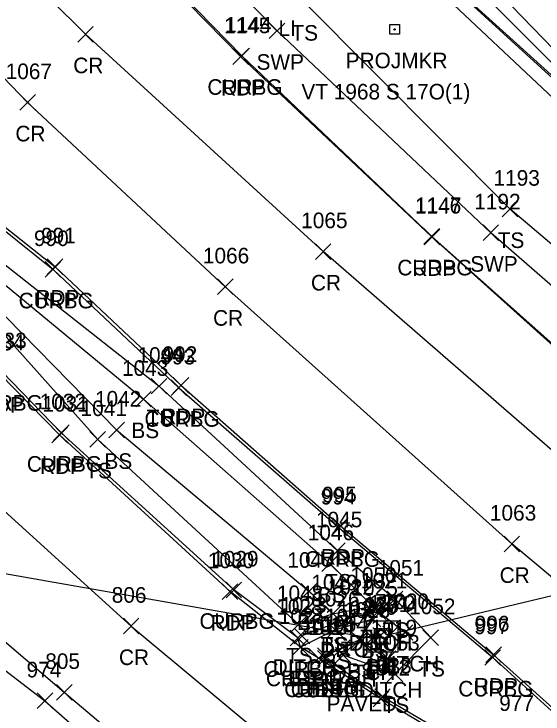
# Model space of a CAD drawing. Extents: x 1688195 to 1692013, y 424605 to 441234.
# Drawn here: x 1691823.2 to 1691891.2, y 439243.2 to 439333.1 of the extents above; entities that cross this region are included whole.
import ezdxf

# ---------------------------------------------------------------- set-up
doc = ezdxf.new("R2010")
doc.units = 0
for name, color, linetype in [('D_A', 7, 'Continuous'), ('D_C', 7, 'Continuous'), ('D_I', 7, 'Continuous'), ('D_TIC', 7, 'Continuous'), ('DCP', 7, 'Continuous'), ('DD', 7, 'Continuous'), ('DS', 7, 'Continuous'), ('L_A', 7, 'Continuous'), ('L_I', 7, 'Continuous'), ('L_TIC', 7, 'Continuous'), ('LELB', 7, 'Continuous'), ('P_A', 7, 'Continuous'), ('P_I', 7, 'Continuous'), ('P_TIC', 7, 'Continuous'), ('PET', 7, 'Continuous'), ('PRC', 7, 'Continuous'), ('PSP', 7, 'Continuous'), ('R_A', 7, 'Continuous'), ('R_I', 7, 'Continuous'), ('R_TIC', 7, 'Continuous'), ('RC', 7, 'Continuous'), ('RSW', 7, 'Continuous'), ('S_A', 7, 'Continuous'), ('S_C', 7, 'Continuous'), ('S_I', 7, 'Continuous'), ('SRM', 7, 'Continuous'), ('U_A', 7, 'Continuous')]:
    doc.layers.add(name, color=color, linetype=linetype)

msp = doc.modelspace()

# ---------------------------------------------------------------- linework, layer by layer
at = {"layer": 'D_TIC'}
for points in [[(1691869.012, 439255.339), (1691871.012, 439257.339)], [(1691871.012, 439255.339), (1691869.012, 439257.339)], [(1691865.312, 439254.525), (1691867.312, 439256.525)], [(1691867.312, 439254.525), (1691865.312, 439256.525)], [(1691859.231, 439252.243), (1691861.231, 439254.243)], [(1691861.231, 439252.243), (1691859.231, 439254.243)], [(1691869.335, 439252.313), (1691871.335, 439254.313)], [(1691871.335, 439252.313), (1691869.335, 439254.313)], [(1691870.629, 439252.485), (1691872.629, 439254.485)], [(1691872.629, 439252.485), (1691870.629, 439254.485)], [(1691872.466, 439252.691), (1691874.466, 439254.691)], [(1691874.466, 439252.691), (1691872.466, 439254.691)], [(1691866.813, 439251.57), (1691868.813, 439253.57)], [(1691868.813, 439251.57), (1691866.813, 439253.57)], [(1691868.305, 439251.966), (1691870.305, 439253.966)], [(1691870.305, 439251.966), (1691868.305, 439253.966)], [(1691864.421, 439250.736), (1691866.421, 439252.736)], [(1691866.421, 439250.736), (1691864.421, 439252.736)], [(1691862.225, 439249.714), (1691864.225, 439251.714)], [(1691864.225, 439249.714), (1691862.225, 439251.714)], [(1691870.288, 439249.327), (1691872.288, 439251.327)], [(1691872.288, 439249.327), (1691870.288, 439251.327)]]:
    msp.add_lwpolyline(points, dxfattribs=at)
at = {"layer": 'DCP'}
for points in [[(1691949.159, 439273.864), (1691789.035, 439418.458)], [(1691774.059, 439269.686), (1691869.305, 439252.966)], [(1691871.629, 439253.485), (1691919.551, 439264.923)]]:
    msp.add_lwpolyline(points, dxfattribs=at)
at = {"layer": 'DD'}
for points in [[(1691845.001, 439386.653), (1691846.957, 439371.914), (1691853.76, 439362.044), (1691874.032, 439339.657), (1691896.104, 439318.91), (1691934.444, 439282.927), (1691949.727, 439270.289), (1691969.734, 439279.956), (1691978.582, 439270.803)], [(1691849.482, 439383.397), (1691851.476, 439372.687), (1691857.963, 439364.796), (1691877.631, 439343.986), (1691899.361, 439321.571), (1691937.96, 439287.208), (1691947.813, 439278.163), (1691953.235, 439277.559), (1691972.915, 439286.296), (1691980.771, 439274.159), (1691984.62, 439267.717)], [(1691863.225, 439250.714), (1691865.421, 439251.736), (1691867.813, 439252.57), (1691871.288, 439250.327), (1691873.466, 439253.691), (1691870.012, 439256.339), (1691866.312, 439255.525), (1691860.231, 439253.243)]]:
    msp.add_lwpolyline(points, dxfattribs=at)
at = {"layer": 'DS'}
for p, q in [((1691868.561, 439255.182), (1691872.561, 439255.182)), ((1691868.561, 439251.182), (1691868.561, 439255.182)), ((1691872.561, 439255.182), (1691872.561, 439251.182)), ((1691869.561, 439252.182), (1691869.561, 439254.182)), ((1691869.561, 439254.182), (1691871.561, 439254.182)), ((1691871.561, 439254.182), (1691871.561, 439252.182)), ((1691870.566, 439253.183), (1691870.566, 439253.183)), ((1691870.566, 439253.183), (1691870.566, 439253.183)), ((1691871.561, 439252.182), (1691869.561, 439252.182)), ((1691872.561, 439251.182), (1691868.561, 439251.182))]:
    msp.add_line(p, q, dxfattribs=at)
at = {"layer": 'L_TIC'}
for points in [[(1691885.972, 439307.046), (1691887.972, 439309.046)], [(1691887.972, 439307.046), (1691885.972, 439309.046)], [(1691840.88, 439284.31), (1691842.88, 439286.31)], [(1691842.88, 439284.31), (1691840.88, 439286.31)], [(1691838.882, 439282.636), (1691840.882, 439284.636)], [(1691840.882, 439282.636), (1691838.882, 439284.636)], [(1691835.42, 439278.689), (1691837.42, 439280.689)], [(1691837.42, 439278.689), (1691835.42, 439280.689)], [(1691832.998, 439277.476), (1691834.998, 439279.476)], [(1691834.998, 439277.476), (1691832.998, 439279.476)], [(1691863.803, 439263.192), (1691865.803, 439265.192)], [(1691865.803, 439263.192), (1691863.803, 439265.192)], [(1691862.807, 439261.535), (1691864.807, 439263.535)], [(1691864.807, 439261.535), (1691862.807, 439263.535)], [(1691860.134, 439257.993), (1691862.134, 439259.993)], [(1691862.134, 439257.993), (1691860.134, 439259.993)], [(1691871.176, 439256.99), (1691873.176, 439258.99)], [(1691873.176, 439256.99), (1691871.176, 439258.99)], [(1691868.31, 439256.053), (1691870.31, 439258.053)], [(1691870.31, 439256.053), (1691868.31, 439258.053)], [(1691868.31, 439256.053), (1691870.31, 439258.053)], [(1691870.31, 439256.053), (1691868.31, 439258.053)], [(1691863.22, 439255.101), (1691865.22, 439257.101)], [(1691865.22, 439255.101), (1691863.22, 439257.101)], [(1691863.22, 439255.101), (1691865.22, 439257.101)], [(1691865.22, 439255.101), (1691863.22, 439257.101)], [(1691868.369, 439254.401), (1691870.369, 439256.401)], [(1691870.369, 439254.401), (1691868.369, 439256.401)], [(1691858.792, 439253.715), (1691860.792, 439255.715)], [(1691860.792, 439253.715), (1691858.792, 439255.715)], [(1691863.516, 439253.027), (1691865.516, 439255.027)], [(1691865.516, 439253.027), (1691863.516, 439255.027)], [(1691866.598, 439251.737), (1691868.598, 439253.737)], [(1691868.598, 439251.737), (1691866.598, 439253.737)], [(1691875.774, 439252.036), (1691877.774, 439254.036)], [(1691877.774, 439252.036), (1691875.774, 439254.036)], [(1691859.033, 439250.797), (1691861.033, 439252.797)], [(1691861.033, 439250.797), (1691859.033, 439252.797)], [(1691864.531, 439249.784), (1691866.531, 439251.784)], [(1691866.531, 439249.784), (1691864.531, 439251.784)], [(1691861.377, 439249.392), (1691863.377, 439251.392)], [(1691863.377, 439249.392), (1691861.377, 439251.392)], [(1691871.187, 439247.373), (1691873.187, 439249.373)], [(1691873.187, 439247.373), (1691871.187, 439249.373)]]:
    msp.add_lwpolyline(points, dxfattribs=at)
at = {"layer": 'LELB'}
for points in [[(1691975.613, 439270.604), (1691971.416, 439266.02), (1691960.529, 439259.243), (1691939.22, 439264.039), (1691915.683, 439283.723), (1691886.972, 439308.046), (1691860.472, 439334.665), (1691845.989, 439348.301), (1691840.055, 439356.702), (1691834.354, 439370.122), (1691833.776, 439391.583)], [(1691846.65, 439384.738), (1691848.676, 439371.881), (1691855.161, 439363.031), (1691875.02, 439340.722), (1691897.71, 439320.027), (1691935.729, 439284.323), (1691949.052, 439272.369), (1691970.057, 439281.458), (1691980.121, 439271.732), (1691983.031, 439266.506)], [(1691847.582, 439384.469), (1691849.654, 439372.104), (1691856.364, 439363.867), (1691876.408, 439342.833), (1691898.398, 439320.717), (1691936.438, 439285.395), (1691950.074, 439275.355), (1691972.127, 439284.543), (1691980.121, 439271.732)], [(1691816.816, 439305.046), (1691813.249, 439301.655), (1691833.998, 439278.476), (1691859.792, 439254.715), (1691864.22, 439256.101), (1691869.31, 439257.053)], [(1691816.816, 439305.046), (1691841.88, 439285.31), (1691864.803, 439264.192), (1691872.176, 439257.99), (1691876.774, 439253.036), (1691872.187, 439248.373), (1691865.531, 439250.784)], [(1691819.881, 439300.105), (1691818.164, 439298.257), (1691836.42, 439279.689), (1691861.134, 439258.993), (1691864.22, 439256.101)], [(1691819.881, 439300.105), (1691839.882, 439283.636), (1691863.807, 439262.535), (1691869.31, 439257.053)], [(1691862.377, 439250.392), (1691867.598, 439252.737), (1691869.369, 439255.401), (1691864.516, 439254.027), (1691860.033, 439251.797)]]:
    msp.add_lwpolyline(points, dxfattribs=at)
at = {"layer": 'P_TIC'}
for points in [[(1691831.423, 439329.487), (1691833.423, 439331.487)], [(1691833.423, 439329.487), (1691831.423, 439331.487)], [(1691851.353, 439326.623), (1691853.353, 439328.623)], [(1691853.353, 439326.623), (1691851.353, 439328.623)], [(1691823.991, 439320.732), (1691825.991, 439322.732)], [(1691825.991, 439320.732), (1691823.991, 439322.732)], [(1691875.927, 439303.468), (1691877.927, 439305.468)], [(1691877.927, 439303.468), (1691875.927, 439305.468)], [(1691861.957, 439301.592), (1691863.957, 439303.592)], [(1691863.957, 439301.592), (1691861.957, 439303.592)], [(1691827.512, 439299.647), (1691829.512, 439301.647)], [(1691829.512, 439299.647), (1691827.512, 439301.647)], [(1691849.384, 439297.072), (1691851.384, 439299.072)], [(1691851.384, 439297.072), (1691849.384, 439299.072)], [(1691843.684, 439284.422), (1691845.684, 439286.422)], [(1691845.684, 439284.422), (1691843.684, 439286.422)], [(1691828.097, 439278.042), (1691830.097, 439280.042)], [(1691830.097, 439278.042), (1691828.097, 439280.042)], [(1691864.174, 439266.394), (1691866.174, 439268.394)], [(1691866.174, 439266.394), (1691864.174, 439268.394)], [(1691886.198, 439264.051), (1691888.198, 439266.051)], [(1691888.198, 439264.051), (1691886.198, 439266.051)], [(1691850.002, 439257.938), (1691852.002, 439259.938)], [(1691852.002, 439257.938), (1691850.002, 439259.938)], [(1691837.297, 439253.51), (1691839.297, 439255.51)], [(1691839.297, 439253.51), (1691837.297, 439255.51)], [(1691859.033, 439250.797), (1691861.033, 439252.797)], [(1691861.033, 439250.797), (1691859.033, 439252.797)], [(1691883.848, 439249.831), (1691885.848, 439251.831)], [(1691885.848, 439249.831), (1691883.848, 439251.831)], [(1691861.377, 439249.392), (1691863.377, 439251.392)], [(1691863.377, 439249.392), (1691861.377, 439251.392)], [(1691828.698, 439245.009), (1691830.698, 439247.009)], [(1691830.698, 439245.009), (1691828.698, 439247.009)], [(1691869.381, 439244.165), (1691871.381, 439246.165)], [(1691871.381, 439244.165), (1691869.381, 439246.165)], [(1691826.219, 439243.924), (1691828.219, 439245.924)], [(1691828.219, 439243.924), (1691826.219, 439245.924)]]:
    msp.add_lwpolyline(points, dxfattribs=at)
at = {"layer": 'PET'}
for points in [[(1691827.559, 439394.955), (1691825.961, 439390.443), (1691824.493, 439382.805), (1691824.197, 439378.066), (1691824.28, 439373.817), (1691824.909, 439368.552), (1691826.714, 439361.575), (1691828.277, 439357.551), (1691830.285, 439353.486), (1691834.62, 439346.713), (1691838.982, 439341.279), (1691852.353, 439327.623), (1691876.927, 439304.468), (1691895.87, 439287.457)], [(1691703.519, 439378.215), (1691727.927, 439348.964), (1691752.514, 439320.765), (1691774.827, 439296.788), (1691803.993, 439267.935), (1691829.698, 439246.009), (1691860.192, 439220.256)], [(1691800.945, 439315.05), (1691800.709, 439316.533), (1691801.542, 439317.586), (1691803.007, 439317.751), (1691817.064, 439309.697), (1691828.512, 439300.647), (1691844.684, 439285.422), (1691865.174, 439267.394), (1691884.848, 439250.831), (1691897.532, 439239.425), (1691910.299, 439227.429), (1691911.518, 439225.273), (1691910.888, 439223.79), (1691909.812, 439223.418), (1691908.764, 439223.597), (1691890.09, 439233.403), (1691870.381, 439245.165), (1691862.377, 439250.392), (1691860.033, 439251.797), (1691851.002, 439258.938), (1691829.097, 439279.042), (1691821.385, 439286.908), (1691810.775, 439300.426)]]:
    msp.add_lwpolyline(points, dxfattribs=at)
at = {"layer": 'PRC'}
for points in [[(1691980.661, 439193.959), (1691949.028, 439215.605), (1691915.391, 439241.551), (1691887.198, 439265.051), (1691850.384, 439298.072), (1691824.991, 439321.732), (1691796.941, 439350.893), (1691771.504, 439379.218), (1691742.052, 439414.412)], [(1691713.182, 439386.477), (1691737.313, 439357.714), (1691761.172, 439330.745), (1691784.31, 439305.517), (1691812.134, 439278.202), (1691838.297, 439254.51), (1691867.441, 439230.247), (1691889.259, 439214.415), (1691920.444, 439189.798), (1691954.552, 439163.68)], [(1691957.024, 439223.443), (1691923.547, 439249.723), (1691894.348, 439275.353), (1691862.957, 439302.592), (1691832.423, 439330.487), (1691805.17, 439357.497)]]:
    msp.add_lwpolyline(points, dxfattribs=at)
at = {"layer": 'PSP'}
msp.add_lwpolyline([(1691696.132, 439372.686), (1691709.548, 439355.191), (1691723.603, 439339.325), (1691742.747, 439319), (1691750.974, 439309.526), (1691763.384, 439297.713), (1691773.94, 439286.942), (1691807.317, 439260.152), (1691827.219, 439244.924), (1691853.912, 439221.372)], dxfattribs=at)
at = {"layer": 'R_TIC'}
for points in [[(1691856.041, 439329.929), (1691858.041, 439331.929)], [(1691858.041, 439329.929), (1691856.041, 439331.929)], [(1691851.504, 439326.715), (1691853.504, 439328.715)], [(1691853.504, 439326.715), (1691851.504, 439328.715)], [(1691875.907, 439303.531), (1691877.907, 439305.531)], [(1691877.907, 439303.531), (1691875.907, 439305.531)], [(1691883.494, 439304.003), (1691885.494, 439306.003)], [(1691885.494, 439304.003), (1691883.494, 439306.003)], [(1691827.254, 439299.3), (1691829.254, 439301.3)], [(1691829.254, 439299.3), (1691827.254, 439301.3)], [(1691843.418, 439284.107), (1691845.418, 439286.107)], [(1691845.418, 439284.107), (1691843.418, 439286.107)], [(1691828.315, 439278.332), (1691830.315, 439280.332)], [(1691830.315, 439278.332), (1691828.315, 439280.332)], [(1691864.016, 439266.121), (1691866.016, 439268.121)], [(1691866.016, 439266.121), (1691864.016, 439268.121)], [(1691850.486, 439258.157), (1691852.486, 439260.157)], [(1691852.486, 439258.157), (1691850.486, 439260.157)], [(1691858.706, 439251.995), (1691860.706, 439253.995)], [(1691860.706, 439251.995), (1691858.706, 439253.995)], [(1691859.033, 439250.797), (1691861.033, 439252.797)], [(1691861.033, 439250.797), (1691859.033, 439252.797)], [(1691883.737, 439249.475), (1691885.737, 439251.475)], [(1691885.737, 439249.475), (1691883.737, 439251.475)], [(1691861.377, 439249.392), (1691863.377, 439251.392)], [(1691863.377, 439249.392), (1691861.377, 439251.392)], [(1691862.213, 439249.357), (1691864.213, 439251.357)], [(1691864.213, 439249.357), (1691862.213, 439251.357)], [(1691869.585, 439244.445), (1691871.585, 439246.445)], [(1691871.585, 439244.445), (1691869.585, 439246.445)]]:
    msp.add_lwpolyline(points, dxfattribs=at)
at = {"layer": 'RC'}
for points in [[(1691827.698, 439394.916), (1691826.17, 439390.373), (1691824.809, 439382.88), (1691824.344, 439378.115), (1691824.336, 439373.749), (1691825.062, 439368.496), (1691826.846, 439361.604), (1691828.402, 439357.538), (1691830.439, 439353.686), (1691834.776, 439346.958), (1691839.157, 439341.394), (1691852.504, 439327.715), (1691876.907, 439304.531), (1691896.006, 439287.533), (1691912.05, 439273.882), (1691927.887, 439261.022), (1691934.61, 439255.828), (1691939.482, 439252.554), (1691945.382, 439250.443), (1691949.024, 439249.75)], [(1691801.246, 439315.044), (1691801.115, 439316.331), (1691801.764, 439317.377), (1691802.82, 439317.349), (1691816.869, 439309.413), (1691828.254, 439300.3), (1691844.418, 439285.107), (1691865.016, 439267.121), (1691884.737, 439250.475), (1691897.458, 439238.929), (1691910.163, 439227.134), (1691911.269, 439225.368), (1691910.647, 439224.032), (1691909.839, 439223.784), (1691908.933, 439223.978), (1691890.407, 439233.729), (1691870.585, 439245.445), (1691863.213, 439250.357), (1691862.377, 439250.392)], [(1691860.033, 439251.797), (1691859.706, 439252.995), (1691851.486, 439259.157), (1691829.315, 439279.332), (1691821.702, 439287.165), (1691811.14, 439300.575)]]:
    msp.add_lwpolyline(points, dxfattribs=at)
at = {"layer": 'RSW'}
msp.add_lwpolyline([(1691977.456, 439268.158), (1691972.672, 439263.178), (1691966.618, 439257.976), (1691961.856, 439255.834), (1691956.783, 439255.299), (1691947.569, 439255.86), (1691941.633, 439257.352), (1691936.742, 439260.655), (1691912.896, 439280.301), (1691884.494, 439305.003), (1691857.041, 439330.929), (1691842.614, 439345.598), (1691837.427, 439352.308), (1691833.754, 439359.527), (1691830.576, 439369.096), (1691830.336, 439383.859), (1691832.593, 439392.597)], dxfattribs=at)
at = {"layer": 'SRM'}
msp.add_lwpolyline([(1691871.506, 439331.741), (1691872.756, 439331.741), (1691872.756, 439330.491), (1691871.506, 439330.491)], close=True, dxfattribs=at)
msp.add_circle((1691872.131, 439331.116), 0.0833, dxfattribs=at)

# ---------------------------------------------------------------- texts
at = {"layer": 'D_A'}
for s, p in [('DITCH', (1691866.248, 439251.339)), ('DITCH', (1691862.549, 439250.525)), ('DITCH', (1691869.703, 439248.691)), ('DITCH', (1691856.467, 439248.243)), ('DIB', (1691868.437, 439248.313)), ('P', (1691868.683, 439247.966)), ('DI', (1691869.621, 439248.183)), ('P', (1691871.007, 439248.485)), ('DITCH', (1691861.657, 439246.736)), ('DITCH', (1691864.05, 439247.57)), ('DITCH', (1691859.461, 439245.714)), ('DITCH', (1691867.525, 439245.327))]:
    msp.add_text(s, height=2, dxfattribs=at).set_placement(p)
at = {"layer": 'D_C'}
msp.add_text('PAVED', height=2, dxfattribs=at).set_placement((1691863.396, 439243.57))
at = {"layer": 'D_I'}
for s, p in [('1021', (1691867.807, 439259.339)), ('1022', (1691863.541, 439258.525)), ('1020', (1691870.608, 439256.691)), ('1023', (1691857.459, 439256.243)), ('1269', (1691866.557, 439255.966)), ('978', (1691868.204, 439256.183)), ('1271', (1691868.209, 439256.313)), ('1270', (1691868.85, 439256.485)), ('1018', (1691865.609, 439255.57)), ('1017', (1691863.216, 439254.736)), ('1016', (1691860.965, 439253.714)), ('1019', (1691869.076, 439253.327))]:
    msp.add_text(s, height=2, dxfattribs=at).set_placement(p)
at = {"layer": 'L_A'}
for s, p in [('TS', (1691858.882, 439329.665)), ('TS', (1691885.381, 439303.046)), ('TS', (1691840.289, 439280.31)), ('BS', (1691838.323, 439278.636)), ('BS', (1691834.861, 439274.689)), ('TS', (1691832.408, 439273.476)), ('TS', (1691863.212, 439259.192)), ('BS', (1691862.248, 439257.535)), ('BS', (1691859.575, 439253.993)), ('TS', (1691870.585, 439252.99)), ('TS', (1691867.72, 439252.053)), ('BS', (1691867.751, 439252.053)), ('TS', (1691862.63, 439251.101)), ('BS', (1691862.661, 439251.101)), ('BS', (1691867.81, 439250.401)), ('TS', (1691858.201, 439249.715)), ('BS', (1691862.957, 439249.027)), ('BS', (1691866.039, 439247.737)), ('TS', (1691875.183, 439248.036)), ('BS', (1691858.474, 439246.797)), ('BS', (1691860.818, 439245.392)), ('TS', (1691863.941, 439245.784)), ('TS', (1691870.597, 439243.373))]:
    msp.add_text(s, height=2, dxfattribs=at).set_placement(p)
at = {"layer": 'L_I'}
for s, p in [('1193', (1691884.846, 439311.046)), ('1044', (1691839.108, 439288.31)), ('1043', (1691837.111, 439286.636)), ('1042', (1691833.649, 439282.689)), ('1041', (1691831.793, 439281.476)), ('1045', (1691862.031, 439267.192)), ('1046', (1691860.98, 439265.535)), ('1047', (1691858.362, 439261.993)), ('1051', (1691869.971, 439260.99)), ('1050', (1691866.452, 439260.053)), ('1050', (1691866.452, 439260.053)), ('1049', (1691861.441, 439259.101)), ('1049', (1691861.441, 439259.101)), ('1025', (1691866.597, 439258.401)), ('1048', (1691857.02, 439257.715)), ('1026', (1691861.689, 439257.027)), ('1024', (1691864.827, 439255.737)), ('1052', (1691874.002, 439256.036)), ('1027', (1691857.262, 439254.797)), ('1015', (1691860.172, 439253.392)), ('1054', (1691862.76, 439253.784)), ('1053', (1691869.416, 439251.373))]:
    msp.add_text(s, height=2, dxfattribs=at).set_placement(p)
at = {"layer": 'P_A'}
for s, p in [('CR', (1691830.856, 439325.487)), ('RDP', (1691849.841, 439322.623)), ('CR', (1691823.424, 439316.732)), ('RDP', (1691874.415, 439299.468)), ('CR', (1691861.39, 439297.592)), ('RDP', (1691826, 439295.647)), ('CR', (1691848.817, 439293.072)), ('RDP', (1691818.873, 439281.908)), ('RDP', (1691842.172, 439280.422)), ('RDP', (1691826.585, 439274.042)), ('RDP', (1691862.662, 439262.394)), ('CR', (1691885.631, 439260.051)), ('RDP', (1691848.49, 439253.938)), ('CR', (1691836.73, 439249.51)), ('RDP', (1691857.521, 439246.797)), ('RDP', (1691859.865, 439245.392)), ('RDP', (1691882.336, 439245.831))]:
    msp.add_text(s, height=2, dxfattribs=at).set_placement(p)
at = {"layer": 'P_I'}
for s, p in [('1145', (1691850.227, 439330.623)), ('1067', (1691822.172, 439324.732)), ('1146', (1691874.746, 439307.468)), ('1065', (1691860.138, 439305.592)), ('991', (1691826.717, 439303.647)), ('1066', (1691847.51, 439301.072)), ('1034', (1691818.614, 439289.908)), ('992', (1691842.322, 439288.422)), ('1031', (1691826.892, 439282.042)), ('995', (1691862.812, 439270.394)), ('1063', (1691884.379, 439268.051)), ('1030', (1691848.143, 439261.938)), ('806', (1691835.801, 439257.51)), ('1027', (1691857.262, 439254.797)), ('1015', (1691860.172, 439253.392)), ('996', (1691882.43, 439253.831)), ('805', (1691827.257, 439249.009)), ('974', (1691824.857, 439247.924)), ('1012', (1691868.176, 439248.165))]:
    msp.add_text(s, height=2, dxfattribs=at).set_placement(p)
at = {"layer": 'R_A'}
for s, p in [('SWP', (1691854.403, 439325.929)), ('CURBG', (1691848.087, 439322.715)), ('SWP', (1691881.856, 439300.003)), ('CURBG', (1691872.49, 439299.531)), ('CURBG', (1691823.836, 439295.3)), ('CURBG', (1691817.284, 439282.165)), ('CURBG', (1691840.001, 439280.107)), ('CURBG', (1691824.897, 439274.332)), ('CURBG', (1691860.598, 439262.121)), ('CURBG', (1691847.069, 439254.157)), ('CURBG', (1691855.289, 439247.995)), ('CURBG', (1691855.616, 439246.797)), ('CURBG', (1691857.96, 439245.392)), ('CURBG', (1691858.795, 439245.357)), ('CURBG', (1691880.319, 439245.475))]:
    msp.add_text(s, height=2, dxfattribs=at).set_placement(p)
at = {"layer": 'R_I'}
for s, p in [('1144', (1691850.378, 439330.715)), ('1192', (1691882.368, 439308.003)), ('1147', (1691874.781, 439307.531)), ('990', (1691825.805, 439303.3)), ('1033', (1691818.93, 439290.165)), ('993', (1691842.056, 439288.107)), ('1032', (1691826.543, 439282.332)), ('994', (1691862.654, 439270.121)), ('1029', (1691848.706, 439262.157)), ('1028', (1691856.935, 439255.995)), ('1027', (1691857.262, 439254.797)), ('1015', (1691860.172, 439253.392)), ('1014', (1691861.008, 439253.357)), ('997', (1691882.374, 439253.475)), ('1013', (1691868.381, 439248.445))]:
    msp.add_text(s, height=2, dxfattribs=at).set_placement(p)
at = {"layer": 'S_A'}
msp.add_text('PROJMKR', height=2, dxfattribs=at).set_placement((1691865.855, 439326.116))
at = {"layer": 'S_C'}
msp.add_text('VT 1968 S 17O(1)', height=2, dxfattribs=at).set_placement((1691860.162, 439322.116))
at = {"layer": 'S_I'}
msp.add_text('977', height=2, dxfattribs=at).set_placement((1691885.574, 439243.618))
at = {"layer": 'U_A'}
msp.add_text('LI', height=2, dxfattribs=at).set_placement((1691857.223, 439330.253))

doc.saveas('drawing.dxf')
